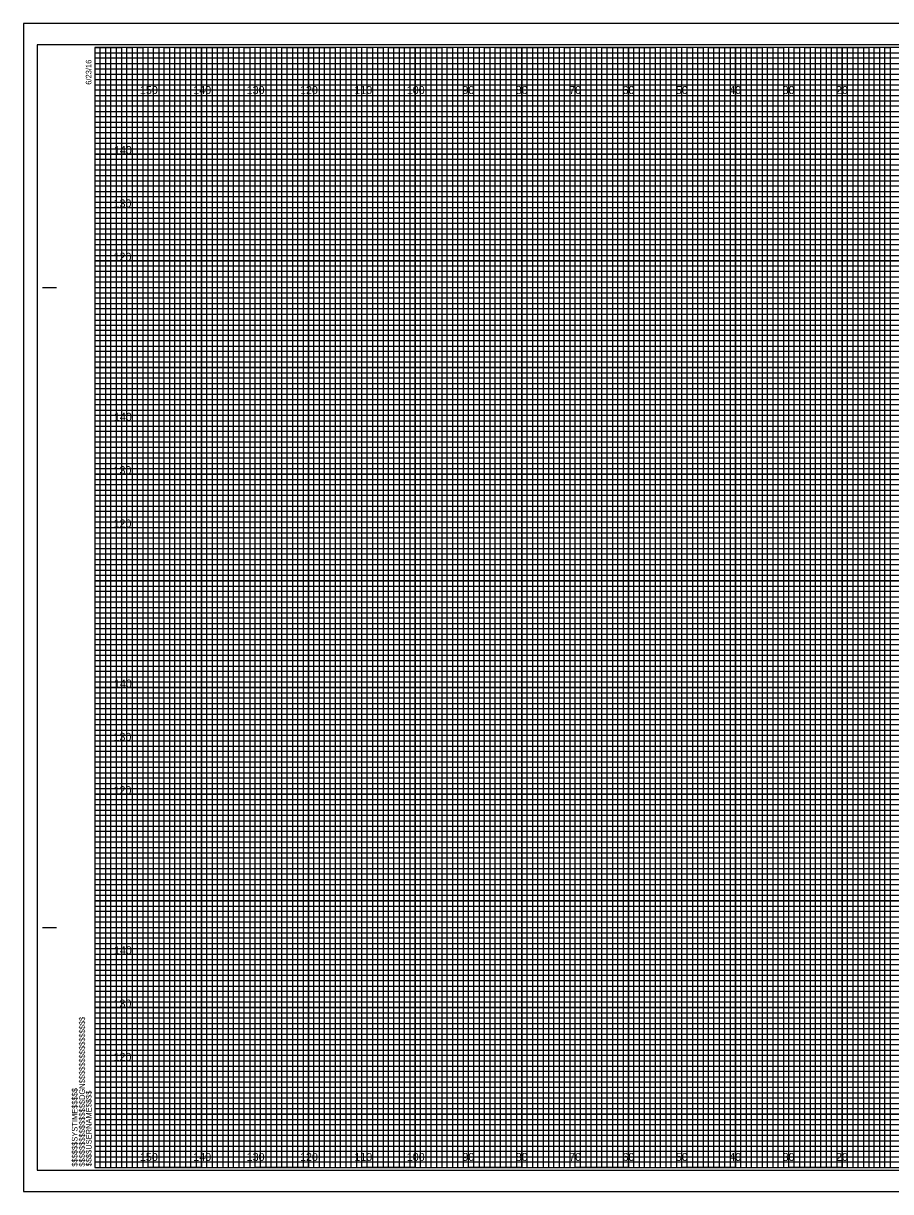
# Model space of a CAD drawing. Extents: x -13 to 329, y -17 to 10994.
# Drawn here: x -13.4 to 149.1, y 6155.5 to 6374.5 of the extents above; entities that cross this region are included whole.
import ezdxf

# ---------------------------------------------------------------- set-up
doc = ezdxf.new("R2010")
doc.units = 0
for name, color, linetype in [('Prop XS Elevation Labels', 7, 'Continuous'), ('Prop XS Offset Labels', 7, 'Continuous'), ('Sheet Cross Section CELL', 7, 'Continuous'), ('Sheet Cross Section Grid Major CELL', 7, 'Continuous'), ('Sheet Cross Section Grid Middle CELL', 7, 'Continuous'), ('Sheet Cross Section Grid Minor 1 CELL', 7, 'Continuous'), ('Sheet Cross Section Grid Minor 2 CELL', 7, 'Continuous'), ('Sheet Cutting Line CELL', 7, 'Continuous'), ('Sheet DOT Grid CELL', 7, 'Continuous'), ('Sheet Plot Border Inside CELL', 7, 'Continuous'), ('Sheet Plot Border Outside CELL', 7, 'Continuous')]:
    doc.layers.add(name, color=color, linetype=linetype)

msp = doc.modelspace()

# ---------------------------------------------------------------- linework, layer by layer
at = {"layer": 'Sheet Cross Section CELL'}
for p, q in [((-9.8, 6325), (-7.3, 6325)), ((-9.7, 6325), (-7.2, 6325)), ((-9.8, 6205), (-7.3, 6205)), ((-9.7, 6205), (-7.2, 6205)), ((0, 6160), (0, 6160)), ((0, 6160), (0, 6160)), ((0, 6160), (0, 6160)), ((0, 6160), (0, 6160)), ((0, 6160), (0, 6160)), ((0, 6160), (0, 6160)), ((0, 6160), (0, 6160))]:
    msp.add_line(p, q, dxfattribs=at)
msp.add_lwpolyline([(320, 6370), (0, 6370), (0, 6160), (320, 6160)], close=True, dxfattribs=at)
at = {"layer": 'Sheet Cross Section Grid Major CELL'}
for p, q in [((10, 6370), (0, 6370)), ((10, 6160), (10, 6370)), ((30, 6370), (20, 6370)), ((20, 6370), (20, 6160)), ((30, 6160), (30, 6370)), ((50, 6370), (40, 6370)), ((40, 6370), (40, 6160)), ((50, 6160), (50, 6370)), ((70, 6370), (60, 6370)), ((60, 6370), (60, 6160)), ((70, 6160), (70, 6370)), ((90, 6370), (80, 6370)), ((80, 6370), (80, 6160)), ((90, 6160), (90, 6370)), ((110, 6370), (100, 6370)), ((100, 6370), (100, 6160)), ((110, 6160), (110, 6370)), ((130, 6370), (120, 6370)), ((120, 6370), (120, 6160)), ((130, 6160), (130, 6370)), ((150, 6370), (140, 6370)), ((140, 6370), (140, 6160)), ((20, 6160), (10, 6160)), ((40, 6160), (30, 6160)), ((60, 6160), (50, 6160)), ((80, 6160), (70, 6160)), ((100, 6160), (90, 6160)), ((120, 6160), (110, 6160)), ((140, 6160), (130, 6160))]:
    msp.add_line(p, q, dxfattribs=at)
for points in [[(0, 6360), (320, 6360), (320, 6350), (0, 6350)], [(0, 6340), (320, 6340), (320, 6330), (0, 6330)], [(0, 6320), (320, 6320), (320, 6310), (0, 6310)], [(0, 6300), (320, 6300), (320, 6290), (0, 6290)], [(0, 6280), (320, 6280), (320, 6270), (0, 6270)], [(0, 6260), (320, 6260), (320, 6250), (0, 6250)], [(0, 6240), (320, 6240), (320, 6230), (0, 6230)], [(0, 6220), (320, 6220), (320, 6210), (0, 6210)], [(0, 6200), (320, 6200), (320, 6190), (0, 6190)], [(0, 6180), (320, 6180), (320, 6170), (0, 6170)]]:
    msp.add_lwpolyline(points, dxfattribs=at)
at = {"layer": 'Sheet Cross Section Grid Middle CELL'}
for points in [[(0, 6370), (5, 6370), (5, 6160), (15, 6160), (15, 6370), (25, 6370), (25, 6160), (35, 6160), (35, 6370), (45, 6370), (45, 6160), (55, 6160), (55, 6370), (65, 6370), (65, 6160), (75, 6160), (75, 6370), (85, 6370), (85, 6160), (95, 6160), (95, 6370), (105, 6370), (105, 6160), (115, 6160), (115, 6370), (125, 6370), (125, 6160), (135, 6160), (135, 6370), (145, 6370), (145, 6160), (155, 6160)], [(0, 6365), (275, 6365)], [(0, 6345), (320, 6345), (320, 6355), (0, 6355)], [(0, 6325), (320, 6325), (320, 6335), (0, 6335)], [(0, 6305), (320, 6305), (320, 6315), (0, 6315)], [(0, 6285), (320, 6285), (320, 6295), (0, 6295)], [(0, 6265), (320, 6265), (320, 6275), (0, 6275)], [(0, 6245), (320, 6245), (320, 6255), (0, 6255)], [(0, 6225), (320, 6225), (320, 6235), (0, 6235)], [(0, 6205), (320, 6205), (320, 6215), (0, 6215)], [(0, 6185), (320, 6185), (320, 6195), (0, 6195)], [(0, 6165), (320, 6165), (320, 6175), (0, 6175)]]:
    msp.add_lwpolyline(points, dxfattribs=at)
at = {"layer": 'Sheet Cross Section Grid Minor 1 CELL'}
for p, q in [((0, 6369), (260, 6369)), ((260, 6367.98), (0, 6367.98)), ((0, 6367.98), (0, 6367)), ((0, 6367), (260, 6367)), ((260, 6365.89), (0, 6365.89)), ((0, 6365.89), (0, 6364)), ((0, 6364), (320, 6364))]:
    msp.add_line(p, q, dxfattribs=at)
for points in [[(0, 6363), (270, 6363), (320, 6363), (320, 6362), (0, 6362)], [(0, 6361), (320, 6361), (320, 6359), (0, 6359)], [(0, 6358), (320, 6358), (320, 6357), (0, 6356.98)], [(0, 6356), (320, 6356), (320, 6354), (0, 6354)], [(0, 6353), (320, 6353), (320, 6352), (0, 6352)], [(0, 6351), (320, 6351), (320, 6349), (0, 6349)], [(0, 6348), (320, 6348), (320, 6347), (0, 6347)], [(0, 6346), (320, 6346), (320, 6344), (0, 6344)], [(0, 6343), (320, 6343), (320, 6342), (0, 6342)], [(0, 6341), (320, 6341), (320, 6339), (0, 6339)], [(0, 6338), (320, 6338), (320, 6337), (0, 6337)], [(0, 6336), (320, 6336), (320, 6333.95), (320, 6333), (320, 6332), (0, 6332)], [(0, 6334), (320, 6334), (320, 6333), (0, 6333)], [(0, 6331), (320, 6331), (320, 6329), (0, 6329.03)], [(0, 6329.03), (320, 6329), (320, 6328), (0, 6328)], [(0, 6327), (320, 6327), (320, 6326), (0, 6326)], [(0, 6324), (320, 6324), (320, 6323), (0, 6323)], [(0, 6322), (320, 6322), (320, 6321), (0, 6321)], [(-0.07, 6318.89), (320, 6318.89), (320, 6317.88), (-0.07, 6317.88)], [(0, 6317), (320, 6317), (320, 6316), (0, 6316)], [(0, 6314), (320, 6314), (320, 6313), (0, 6313)], [(0, 6312), (320, 6312), (320, 6311), (0, 6311)], [(0, 6309), (320, 6309), (320, 6308), (0, 6308)], [(0, 6307), (320, 6307), (320, 6306), (0, 6306)], [(0, 6304), (320, 6304), (320, 6303), (0, 6303)], [(0, 6302), (320, 6302), (320, 6301), (0, 6301)], [(0, 6299), (320, 6299), (319.99, 6297.98), (0, 6298)], [(0, 6297), (320, 6297), (320, 6296), (0, 6296)], [(0, 6294), (320, 6294), (320, 6293), (0, 6293)], [(0, 6292), (320, 6292), (320, 6291), (0, 6291)], [(0, 6289), (320, 6289), (320, 6288), (0, 6288)], [(0, 6287), (320, 6287), (320, 6286), (0, 6286)], [(0, 6284), (320, 6284), (320, 6283), (0, 6283)], [(0, 6282), (320, 6282), (320, 6281), (0, 6281)], [(0, 6279), (320, 6279), (320, 6278), (0, 6278)], [(0, 6276.99), (320.07, 6276.91), (320, 6276), (0, 6276)], [(0, 6274), (320, 6274), (320, 6273), (0, 6273)], [(0, 6272), (320, 6272), (320, 6271), (0, 6271)], [(0, 6269), (320, 6269), (320, 6268), (0, 6268)], [(0, 6267), (320, 6267), (320, 6266), (0, 6266)], [(0, 6264), (320, 6264), (320, 6263), (0, 6263)], [(0, 6262), (320, 6262), (320, 6261), (0, 6261)], [(0, 6259), (320, 6259), (320, 6258), (0, 6258)], [(0, 6257), (320, 6257), (320, 6256), (0, 6256)], [(0, 6254), (320, 6254), (320, 6253), (0, 6253)], [(0, 6252), (320, 6252), (320, 6251), (0, 6251)], [(0, 6249), (320, 6249), (320, 6248), (0, 6248)], [(0, 6247), (320, 6247), (320, 6246), (0, 6246)], [(0, 6244), (320, 6244), (320, 6243), (0, 6243)], [(0, 6242), (320, 6242), (320, 6241), (0, 6241)], [(0, 6239), (320, 6239), (319.99, 6237.98), (0, 6238)], [(0, 6237), (320, 6237), (320, 6236), (0, 6236)], [(0, 6234), (320, 6234), (320, 6233), (0, 6233)], [(0, 6232), (320, 6232), (320, 6231), (0, 6231)], [(0, 6229), (320, 6229), (320, 6228), (0, 6228)], [(0, 6227), (320, 6227), (320, 6226), (0, 6226)], [(0, 6224), (320, 6224), (320, 6223), (0, 6223)], [(0, 6222), (320, 6222), (320, 6221), (0, 6221)], [(0, 6219), (320, 6219), (320, 6218), (0, 6218)], [(0, 6216.99), (320.07, 6216.91), (320, 6216), (0, 6216)], [(0, 6214), (320, 6214), (320, 6213), (0, 6213)], [(0, 6212), (320, 6212), (320, 6211), (0, 6211)], [(0, 6209), (320, 6209), (320, 6208), (0, 6208)], [(0, 6207), (320, 6207), (320, 6206), (0, 6206)], [(0, 6204), (320, 6204), (320, 6203), (0, 6203)], [(0, 6202), (320, 6202), (320, 6201), (0, 6201)], [(0, 6199), (320, 6199), (320, 6198), (0, 6198)], [(0, 6197), (320, 6197), (320, 6196), (0, 6196)], [(0, 6194), (320, 6194), (320, 6193), (0, 6193)], [(0, 6192), (320, 6192), (320, 6191), (0, 6191)], [(0, 6189), (320, 6189), (320, 6188), (0, 6188)], [(0, 6187), (320, 6187), (320, 6186), (0, 6186)], [(0, 6184), (320, 6184), (320, 6183), (0, 6183)], [(0, 6182), (320, 6182), (320, 6181), (0, 6181)], [(0, 6179), (320, 6179), (320, 6178), (0, 6178)], [(0, 6177), (320, 6177), (320, 6176), (0, 6176)], [(0, 6174), (320, 6174), (320, 6173), (0, 6173)], [(0, 6172), (320, 6172), (320, 6171), (0, 6171)], [(0, 6169), (320, 6169), (320, 6168), (0, 6168)], [(0, 6167), (320, 6167), (320, 6166), (0, 6166)], [(0, 6164), (320, 6164), (320, 6163), (0, 6163)], [(0, 6162), (320, 6162), (320, 6161), (0, 6161)]]:
    msp.add_lwpolyline(points, dxfattribs=at)
at = {"layer": 'Sheet Cross Section Grid Minor 2 CELL'}
for points in [[(0, 6160), (1, 6160), (1, 6370), (2, 6370), (2, 6160)], [(2, 6160), (3, 6160), (3, 6370), (4, 6370), (4, 6160)], [(5, 6160), (6, 6160), (6, 6370), (7, 6370), (7, 6160)], [(7, 6160), (8, 6160), (8, 6370), (9, 6370), (9, 6160)], [(10, 6160), (11, 6160), (11, 6370), (12, 6370), (12, 6160)], [(12, 6160), (13, 6160), (13, 6370), (14, 6370), (14, 6160)], [(15, 6160), (16, 6160), (16, 6370), (17, 6370), (17, 6160)], [(17, 6160), (18, 6160), (18, 6370), (19, 6370), (19, 6160)], [(20, 6160), (21, 6160), (21, 6370), (22, 6370), (22, 6160)], [(22, 6160), (23, 6160), (23, 6370), (24, 6370), (24, 6160)], [(25, 6160), (26, 6160), (26, 6370), (27, 6370), (27, 6160)], [(27, 6160), (28, 6160), (28, 6370), (29, 6370), (29, 6160)], [(30, 6160), (31, 6160), (31, 6370), (32, 6370), (32, 6160)], [(32, 6160), (33, 6160), (33, 6370), (34, 6370), (34, 6160)], [(35, 6160), (36, 6160), (36, 6370), (37, 6370), (37, 6160)], [(37, 6160), (38, 6160), (38, 6370), (39, 6370), (39, 6160)], [(40, 6160), (41, 6160), (41, 6370), (42, 6370), (42, 6160)], [(42, 6160), (43, 6160), (43, 6370), (44, 6370), (44, 6160)], [(45, 6160), (46, 6160), (46, 6370), (47, 6370), (47, 6160)], [(47, 6160), (48, 6160), (48, 6370), (49, 6370), (49, 6160)], [(50, 6160), (51, 6160), (51, 6370), (52, 6370), (52, 6160)], [(52, 6160), (53, 6160), (53, 6370), (54, 6370), (54, 6160)], [(55, 6160), (56, 6160), (56, 6370), (57, 6370), (57, 6160)], [(57, 6160), (58, 6160), (58, 6370), (59, 6370), (59, 6160)], [(60, 6160), (61, 6160), (61, 6370), (62, 6370), (62, 6160)], [(62, 6160), (63, 6160), (63, 6370), (64, 6370), (64, 6160)], [(65, 6160), (66, 6160), (66, 6370), (67, 6370), (67, 6160)], [(67, 6160), (68, 6160), (68, 6370), (69, 6370), (69, 6160)], [(70, 6160), (71, 6160), (71, 6370), (72, 6370), (72, 6160)], [(72, 6160), (73, 6160), (73, 6370), (74, 6370), (74, 6160)], [(75, 6160), (76, 6160), (76, 6370), (77, 6370), (77, 6160)], [(77, 6160), (78, 6160), (78, 6370), (79, 6370), (79, 6160)], [(80, 6160), (81, 6160), (81, 6370), (82, 6370), (82, 6160)], [(82, 6160), (83, 6160), (83, 6370), (84, 6370), (84, 6160)], [(85, 6160), (86, 6160), (86, 6370), (87, 6370), (87, 6160)], [(87, 6160), (88, 6160), (88, 6370), (89, 6370), (89, 6160)], [(90, 6160), (91, 6160), (91, 6370), (92, 6370), (92, 6160)], [(92, 6160), (93, 6160), (93, 6370), (94, 6370), (94, 6160)], [(95, 6160), (96, 6160), (96, 6370), (97, 6370), (97, 6160)], [(97, 6160), (98, 6160), (98, 6370), (99, 6370), (99, 6160)], [(100, 6160), (101, 6160), (101, 6370), (102, 6370), (102, 6160)], [(102, 6160), (103, 6160), (103, 6370), (104, 6370), (104, 6160)], [(105, 6160), (106, 6160), (106, 6370), (107, 6370), (107, 6160)], [(107, 6160), (108, 6160), (108, 6370), (109, 6370), (109, 6160)], [(110, 6160), (111, 6160), (111, 6370), (112, 6370), (112, 6160)], [(112, 6160), (113, 6160), (113, 6370), (114, 6370), (114, 6160)], [(115, 6160), (116, 6160), (116, 6370), (117, 6370), (117, 6160)], [(117, 6160), (118, 6160), (118, 6370), (119, 6370), (119, 6160)], [(120, 6160), (121, 6160), (121, 6370), (122, 6370), (122, 6160)], [(122, 6160), (123, 6160), (123, 6370), (124, 6370), (124, 6160)], [(125, 6160), (126, 6160), (126, 6370), (127, 6370), (127, 6160)], [(127, 6160), (128, 6160), (128, 6370), (129, 6370), (129, 6160)], [(130, 6160), (131, 6160), (131, 6370), (132, 6370), (132, 6160)], [(132, 6160), (133, 6160), (133, 6370), (134, 6370), (134, 6160)], [(135, 6160), (136, 6160), (136, 6370), (137, 6370), (137, 6160)], [(137, 6160), (138, 6160), (138, 6370), (139, 6370), (139, 6160)], [(140, 6160), (141, 6160), (141, 6370), (142, 6370), (142, 6160)], [(142, 6160), (143, 6160), (143, 6370), (144, 6370), (144, 6160)], [(145, 6160), (146, 6160), (146, 6370), (147, 6370), (147, 6160)], [(147, 6160), (148, 6160), (148, 6370), (149, 6370), (149, 6160)]]:
    msp.add_lwpolyline(points, dxfattribs=at)
at = {"layer": 'Sheet Cutting Line CELL'}
for p, q in [((323.3, 6374.5), (-13.4, 6374.5)), ((-13.4, 6374.5), (-13.4, 6155.5)), ((-13.4, 6155.5), (323.3, 6155.5))]:
    msp.add_line(p, q, dxfattribs=at)
at = {"layer": 'Sheet DOT Grid CELL'}
for p, q in [((10, 6160), (10, 6370)), ((20, 6160), (20, 6370)), ((30, 6160), (30, 6370)), ((40, 6160), (40, 6370)), ((50, 6160), (50, 6370)), ((60, 6160), (60, 6370)), ((70, 6160), (70, 6370)), ((80, 6160), (80, 6370)), ((90, 6160), (90, 6370)), ((100, 6160), (100, 6370)), ((110, 6160), (110, 6370)), ((120, 6160), (120, 6370)), ((130, 6160), (130, 6370)), ((140, 6160), (140, 6370)), ((0, 6360), (320, 6360)), ((0, 6350), (320, 6350)), ((0, 6340), (320, 6340)), ((0, 6330), (320, 6330)), ((0, 6320), (320, 6320)), ((0, 6310), (320, 6310)), ((0, 6300), (320, 6300)), ((0, 6290), (320, 6290)), ((0, 6280), (320, 6280)), ((0, 6270), (320, 6270)), ((0, 6260), (320, 6260)), ((0, 6250), (320, 6250)), ((0, 6240), (320, 6240)), ((0, 6230), (320, 6230)), ((0, 6220), (320, 6220)), ((0, 6210), (320, 6210)), ((0, 6200), (320, 6200)), ((0, 6190), (320, 6190)), ((0, 6180), (320, 6180)), ((0, 6170), (320, 6170))]:
    msp.add_line(p, q, dxfattribs=at)
at = {"layer": 'Sheet Plot Border Inside CELL'}
msp.add_lwpolyline([(-10.8, 6159.5), (322.4, 6159.5), (322.4, 6370.5), (-10.8, 6370.5)], close=True, dxfattribs=at)
at = {"layer": 'Sheet Plot Border Outside CELL'}
msp.add_lwpolyline([(-13.4, 6155.5), (323.3, 6155.5), (323.3, 6374.5), (-13.4, 6374.5)], close=True, dxfattribs=at)

# ---------------------------------------------------------------- texts
at = {"layer": 'Prop XS Elevation Labels'}
for s, p in [('140', (3.57, 6350)), ('130', (3.49, 6340)), ('120', (3.5, 6330)), ('140', (3.57, 6300)), ('130', (3.49, 6290)), ('120', (3.5, 6280)), ('140', (3.57, 6250)), ('130', (3.49, 6240)), ('120', (3.5, 6230)), ('140', (3.57, 6200)), ('130', (3.49, 6190)), ('120', (3.5, 6180))]:
    msp.add_text(s, height=1.5, dxfattribs=at).set_placement(p)
at = {"layer": 'Prop XS Offset Labels'}
for s, p in [('150', (8.44, 6361.25)), ('140', (18.44, 6361.25)), ('130', (28.44, 6361.25)), ('120', (38.44, 6361.25)), ('110', (48.62, 6361.25)), ('100', (58.44, 6361.25)), ('90', (68.86, 6361.25)), ('80', (78.86, 6361.25)), ('70', (88.86, 6361.25)), ('60', (98.86, 6361.25)), ('50', (108.86, 6361.25)), ('40', (118.86, 6361.25)), ('30', (128.86, 6361.25)), ('20', (138.86, 6361.25)), ('150', (8.44, 6161.25)), ('140', (18.44, 6161.25)), ('130', (28.44, 6161.25)), ('120', (38.44, 6161.25)), ('110', (48.62, 6161.25)), ('100', (58.44, 6161.25)), ('90', (68.86, 6161.25)), ('80', (78.86, 6161.25)), ('70', (88.86, 6161.25)), ('60', (98.86, 6161.25)), ('50', (108.86, 6161.25)), ('40', (118.86, 6161.25)), ('30', (128.86, 6161.25)), ('20', (138.86, 6161.25))]:
    msp.add_text(s, height=1.5, dxfattribs=at).set_placement(p)
at = {"layer": 'Sheet Cross Section CELL'}
for s, p in [('6/23/16', (-0.65, 6363)), ('$$$$$$$$$$$$$$$$DGN$$$$$$$$$$$$$$$$', (-1.88, 6160.18)), ('$$$$$$SYSTIME$$$$$', (-3.26, 6160.18)), ('$$$$USERNAME$$$$', (-0.62, 6160.23))]:
    msp.add_text(s, height=1.05, rotation=90, dxfattribs=at).set_placement(p)

doc.saveas('drawing.dxf')
